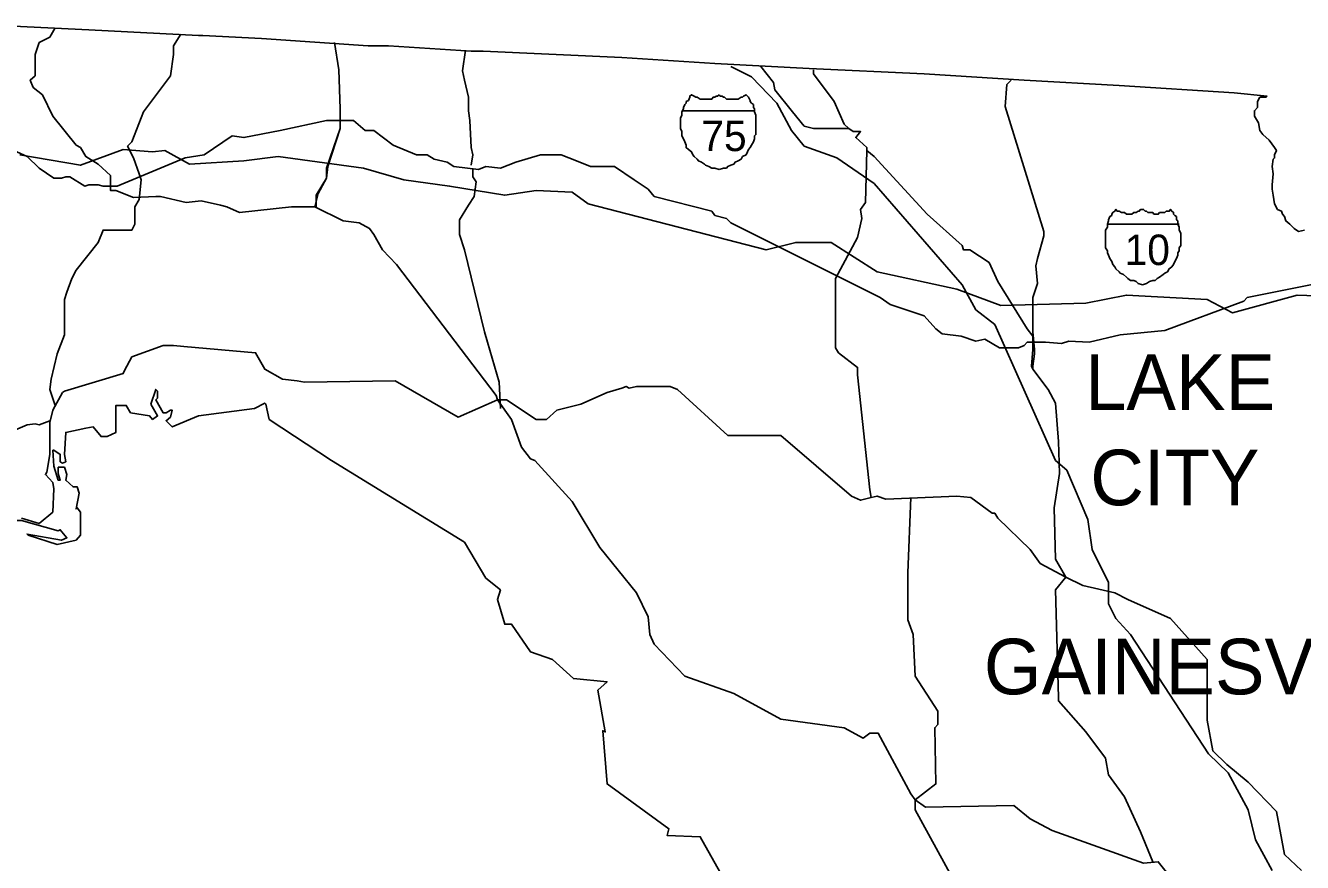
# Model space of a CAD drawing. Extents: x -820.2 to -798.1, y -2199.1 to -2182.2.
# Drawn here: x -807.105 to -806.07, y -2183.909 to -2183.231 of the extents above; entities that cross this region are included whole.
import ezdxf

# ---------------------------------------------------------------- set-up
doc = ezdxf.new("R2010")
doc.units = 0
for name, color, linetype in [('FLMap1', 7, 'Continuous'), ('FLMap2', 7, 'Continuous'), ('FLMap3', 7, 'Continuous'), ('TextMisc', 7, 'Continuous')]:
    doc.layers.add(name, color=color, linetype=linetype)

msp = doc.modelspace()

# ---------------------------------------------------------------- linework, layer by layer
at = {"layer": 'FLMap1'}
for p, q in [((-806.5731, -2183.2999), (-806.5141, -2183.2999)), ((-806.2283, -2183.3917), (-806.1703, -2183.3917))]:
    msp.add_line(p, q, dxfattribs=at)
for points in [[(-806.5429, -2183.287), (-806.5443, -2183.288), (-806.5453, -2183.288), (-806.5463, -2183.289), (-806.5478, -2183.289), (-806.5488, -2183.2905), (-806.5513, -2183.2905), (-806.5523, -2183.2905), (-806.5538, -2183.2905), (-806.5548, -2183.2905), (-806.5558, -2183.2905), (-806.5572, -2183.2905), (-806.5582, -2183.2905), (-806.5607, -2183.289), (-806.5617, -2183.289), (-806.5632, -2183.288), (-806.5652, -2183.287), (-806.5667, -2183.288), (-806.5667, -2183.289), (-806.5677, -2183.2915), (-806.5697, -2183.2925), (-806.5697, -2183.2939), (-806.5706, -2183.2949), (-806.5716, -2183.2974), (-806.5716, -2183.2984), (-806.5731, -2183.3009), (-806.5731, -2183.3034), (-806.5741, -2183.3059), (-806.5741, -2183.3098), (-806.5741, -2183.3123), (-806.5741, -2183.3143), (-806.5731, -2183.3168), (-806.5731, -2183.3192), (-806.5731, -2183.3202), (-806.5716, -2183.3227), (-806.5706, -2183.3252), (-806.5697, -2183.3277), (-806.5697, -2183.3297), (-806.5677, -2183.3312), (-806.5652, -2183.3331), (-806.5642, -2183.3356), (-806.5632, -2183.3371), (-806.5607, -2183.3391), (-806.5597, -2183.3406), (-806.5572, -2183.3416), (-806.5548, -2183.3431), (-806.5538, -2183.3441), (-806.5513, -2183.345), (-806.5488, -2183.3465), (-806.5463, -2183.3465), (-806.5429, -2183.3475)], [(-806.5429, -2183.287), (-806.5419, -2183.288), (-806.5404, -2183.288), (-806.5394, -2183.289), (-806.5384, -2183.289), (-806.5369, -2183.2905), (-806.5359, -2183.2905), (-806.5334, -2183.2905), (-806.5324, -2183.2905), (-806.531, -2183.2905), (-806.53, -2183.2905), (-806.529, -2183.2905), (-806.5275, -2183.2905), (-806.525, -2183.289), (-806.524, -2183.289), (-806.523, -2183.288), (-806.521, -2183.287), (-806.52, -2183.288), (-806.519, -2183.289), (-806.5176, -2183.2915), (-806.5176, -2183.2925), (-806.5166, -2183.2939), (-806.5151, -2183.2949), (-806.5151, -2183.2974), (-806.5141, -2183.2984), (-806.5141, -2183.3009), (-806.5131, -2183.3034), (-806.5131, -2183.3059), (-806.5131, -2183.3098), (-806.5131, -2183.3123), (-806.5131, -2183.3143), (-806.5131, -2183.3168), (-806.5131, -2183.3192), (-806.5141, -2183.3202), (-806.5141, -2183.3227), (-806.5151, -2183.3252), (-806.5166, -2183.3277), (-806.5176, -2183.3297), (-806.519, -2183.3312), (-806.52, -2183.3331), (-806.521, -2183.3356), (-806.524, -2183.3371), (-806.525, -2183.3391), (-806.5275, -2183.3406), (-806.53, -2183.3416), (-806.531, -2183.3431), (-806.5334, -2183.3441), (-806.5359, -2183.345), (-806.5369, -2183.3465), (-806.5394, -2183.3465), (-806.5429, -2183.3475)], [(-806.2, -2183.3798), (-806.2015, -2183.3798), (-806.2025, -2183.3813), (-806.2035, -2183.3813), (-806.205, -2183.3823), (-806.206, -2183.3823), (-806.207, -2183.3823), (-806.2085, -2183.3837), (-806.2095, -2183.3837), (-806.2119, -2183.3837), (-806.2129, -2183.3837), (-806.2144, -2183.3823), (-806.2154, -2183.3823), (-806.2169, -2183.3823), (-806.2189, -2183.3813), (-806.2204, -2183.3813), (-806.2214, -2183.3798), (-806.2224, -2183.3813), (-806.2239, -2183.3823), (-806.2248, -2183.3837), (-806.2248, -2183.3847), (-806.2263, -2183.3857), (-806.2273, -2183.3882), (-806.2273, -2183.3892), (-806.2283, -2183.3917), (-806.2283, -2183.3942), (-806.2298, -2183.3966), (-806.2298, -2183.3991), (-806.2298, -2183.4011), (-806.2298, -2183.4036), (-806.2298, -2183.4066), (-806.2298, -2183.409), (-806.2298, -2183.411), (-806.2283, -2183.4135), (-806.2283, -2183.415), (-806.2273, -2183.417), (-806.2263, -2183.4195), (-806.2248, -2183.4219), (-806.2239, -2183.4244), (-806.2224, -2183.4264), (-806.2214, -2183.4279), (-806.2189, -2183.4304), (-806.2179, -2183.4314), (-806.2154, -2183.4324), (-806.2129, -2183.4348), (-806.2119, -2183.4358), (-806.2095, -2183.4373), (-806.207, -2183.4373), (-806.205, -2183.4383), (-806.2035, -2183.4398), (-806.2, -2183.4408)], [(-806.2, -2183.3798), (-806.199, -2183.3798), (-806.1976, -2183.3813), (-806.1966, -2183.3813), (-806.1956, -2183.3823), (-806.1931, -2183.3823), (-806.1916, -2183.3823), (-806.1906, -2183.3837), (-806.1896, -2183.3837), (-806.1881, -2183.3837), (-806.1871, -2183.3837), (-806.1861, -2183.3823), (-806.1832, -2183.3823), (-806.1817, -2183.3823), (-806.1807, -2183.3813), (-806.1782, -2183.3813), (-806.1772, -2183.3798), (-806.1762, -2183.3813), (-806.1747, -2183.3823), (-806.1747, -2183.3837), (-806.1737, -2183.3847), (-806.1723, -2183.3857), (-806.1723, -2183.3882), (-806.1713, -2183.3892), (-806.1713, -2183.3917), (-806.1703, -2183.3942), (-806.1703, -2183.3966), (-806.1688, -2183.3991), (-806.1688, -2183.4011), (-806.1688, -2183.4036), (-806.1688, -2183.4066), (-806.1688, -2183.409), (-806.1703, -2183.411), (-806.1703, -2183.4135), (-806.1713, -2183.415), (-806.1713, -2183.417), (-806.1723, -2183.4195), (-806.1737, -2183.4219), (-806.1747, -2183.4244), (-806.1762, -2183.4264), (-806.1782, -2183.4279), (-806.1797, -2183.4304), (-806.1817, -2183.4314), (-806.1832, -2183.4324), (-806.1861, -2183.4348), (-806.1881, -2183.4358), (-806.1896, -2183.4373), (-806.1916, -2183.4373), (-806.1941, -2183.4383), (-806.1966, -2183.4398), (-806.2, -2183.4408)]]:
    msp.add_lwpolyline(points, dxfattribs=at)
at = {"layer": 'FLMap2'}
for points in [[(-807.0807, -2183.2329), (-807.0851, -2183.2404), (-807.0936, -2183.2448), (-807.097, -2183.2543), (-807.097, -2183.2632), (-807.097, -2183.2677), (-807.097, -2183.2716), (-807.101, -2183.2751), (-807.0985, -2183.281), (-807.0911, -2183.287), (-807.0826, -2183.3044)], [(-807.0092, -2183.3009), (-806.9874, -2183.2716), (-806.9849, -2183.2543), (-806.9849, -2183.2473), (-806.979, -2183.2379)], [(-806.8544, -2183.2448), (-806.851, -2183.2667), (-806.85, -2183.2984), (-806.85, -2183.3143), (-806.8609, -2183.3465), (-806.8609, -2183.3545), (-806.8678, -2183.3669), (-806.8703, -2183.3778)], [(-806.7483, -2183.2508), (-806.7507, -2183.2677), (-806.7492, -2183.2751), (-806.7458, -2183.289), (-806.7458, -2183.2999), (-806.7448, -2183.3078), (-806.7438, -2183.3297), (-806.7423, -2183.3356), (-806.7438, -2183.3441)], [(-806.5091, -2183.2642), (-806.4987, -2183.2771), (-806.4977, -2183.283), (-806.4833, -2183.3009), (-806.4739, -2183.3123), (-806.4665, -2183.3143), (-806.4377, -2183.3143), (-806.4342, -2183.3168), (-806.4283, -2183.3168), (-806.4322, -2183.3217), (-806.4233, -2183.3297), (-806.4233, -2183.3321), (-806.4173, -2183.3371), (-806.3742, -2183.3837), (-806.3459, -2183.409), (-806.3449, -2183.4125), (-806.3399, -2183.4125), (-806.3241, -2183.4229), (-806.3171, -2183.4383), (-806.2933, -2183.4765), (-806.2888, -2183.4825), (-806.2888, -2183.4934), (-806.2898, -2183.5068), (-806.2888, -2183.5093), (-806.2764, -2183.5256), (-806.2705, -2183.5366), (-806.268, -2183.5678), (-806.267, -2183.5936), (-806.2715, -2183.6214), (-806.2705, -2183.6631), (-806.2621, -2183.6775)], [(-806.4665, -2183.2667), (-806.4665, -2183.2701), (-806.4496, -2183.2925), (-806.4417, -2183.3108), (-806.4377, -2183.3143)], [(-806.3062, -2183.2751), (-806.3097, -2183.2786), (-806.3112, -2183.2964), (-806.2799, -2183.3976), (-806.2799, -2183.4011), (-806.2849, -2183.4195), (-806.2864, -2183.4254), (-806.2849, -2183.4398), (-806.2888, -2183.4512), (-806.2888, -2183.479), (-806.2874, -2183.4934)], [(-807.0807, -2183.5385), (-807.0851, -2183.5256), (-807.0841, -2183.5172), (-807.0792, -2183.4969), (-807.0732, -2183.4815), (-807.0732, -2183.4527), (-807.0712, -2183.4468), (-807.0673, -2183.4358), (-807.0638, -2183.4289), (-807.0459, -2183.4066), (-807.042, -2183.3966), (-807.0186, -2183.3966), (-807.0162, -2183.3917), (-807.0162, -2183.3778), (-807.0127, -2183.3718), (-807.0112, -2183.356), (-807.0127, -2183.351), (-807.0172, -2183.3381), (-807.0221, -2183.3287), (-807.0186, -2183.3252), (-807.0092, -2183.3009)], [(-807.1119, -2183.3331), (-807.1035, -2183.3371), (-807.0936, -2183.3465), (-807.0817, -2183.3545), (-807.0757, -2183.3545), (-807.0722, -2183.3535), (-807.0688, -2183.3535), (-807.0568, -2183.3609), (-807.0534, -2183.3599), (-807.0459, -2183.3599), (-807.042, -2183.3609), (-807.0306, -2183.3609), (-806.9755, -2183.3381), (-806.9601, -2183.3356), (-806.9373, -2183.3202), (-806.9279, -2183.3217), (-806.8986, -2183.3158), (-806.8609, -2183.3078), (-806.839, -2183.3078), (-806.8296, -2183.3158)], [(-806.5954, -2183.732), (-806.5989, -2183.7241), (-806.6004, -2183.7097), (-806.6098, -2183.6903), (-806.6396, -2183.6536), (-806.6619, -2183.6164), (-806.6922, -2183.5832), (-806.6957, -2183.5817), (-806.7031, -2183.5723), (-806.711, -2183.5499), (-806.7225, -2183.5341), (-806.7234, -2183.5306), (-806.8043, -2183.4244), (-806.8157, -2183.4125), (-806.8227, -2183.4001), (-806.8261, -2183.3952), (-806.8346, -2183.3907), (-806.8475, -2183.3892), (-806.8703, -2183.3778), (-806.8892, -2183.3778), (-806.9313, -2183.3823), (-806.9417, -2183.3778), (-806.9467, -2183.3763), (-806.9626, -2183.3728), (-806.9745, -2183.3743), (-806.9953, -2183.3694), (-806.9993, -2183.3694), (-807.0172, -2183.3703), (-807.0315, -2183.3644), (-807.036, -2183.3644), (-807.036, -2183.3525), (-807.0459, -2183.3431), (-807.0559, -2183.3371), (-807.0603, -2183.3297), (-807.0638, -2183.3277), (-807.0826, -2183.3044)], [(-806.8693, -2183.3778), (-806.8693, -2183.3684), (-806.8609, -2183.3545), (-806.8599, -2183.345), (-806.85, -2183.3143)], [(-806.8296, -2183.3158), (-806.8252, -2183.3158), (-806.8227, -2183.3158), (-806.8068, -2183.3277), (-806.7879, -2183.3356), (-806.7795, -2183.3356), (-806.7736, -2183.3391), (-806.7631, -2183.3416), (-806.7577, -2183.345), (-806.7378, -2183.3475), (-806.7319, -2183.345), (-806.72, -2183.3465), (-806.7076, -2183.3416), (-806.6877, -2183.3356), (-806.6709, -2183.3356), (-806.6585, -2183.3406), (-806.647, -2183.345), (-806.6277, -2183.345), (-806.6118, -2183.356), (-806.6004, -2183.3634), (-806.5954, -2183.3694), (-806.5488, -2183.3813), (-806.5463, -2183.3847), (-806.5369, -2183.3872), (-806.5334, -2183.3907), (-806.4124, -2183.4512), (-806.4044, -2183.4567), (-806.3767, -2183.4661), (-806.3672, -2183.4765), (-806.3623, -2183.4805), (-806.3469, -2183.4825), (-806.335, -2183.4864), (-806.3275, -2183.485), (-806.3156, -2183.4919), (-806.3003, -2183.4919), (-806.2958, -2183.4899), (-806.2933, -2183.4874), (-806.2784, -2183.4874), (-806.2655, -2183.4884), (-806.2596, -2183.4864), (-806.2432, -2183.4874)], [(-806.4233, -2183.3321), (-806.4243, -2183.3743), (-806.4283, -2183.3798), (-806.4273, -2183.3872), (-806.4307, -2183.4026), (-806.4486, -2183.4358), (-806.4486, -2183.4919), (-806.4461, -2183.4959), (-806.4307, -2183.5078), (-806.4307, -2183.5137), (-806.4208, -2183.607), (-806.4198, -2183.613)], [(-806.72, -2183.541), (-806.721, -2183.5197), (-806.7304, -2183.4874), (-806.7329, -2183.479), (-806.7492, -2183.4125), (-806.7532, -2183.4001), (-806.7532, -2183.3882), (-806.7458, -2183.3763), (-806.7413, -2183.3694), (-806.7398, -2183.3575), (-806.7423, -2183.3535), (-806.7423, -2183.3475)], [(-806.2432, -2183.4874), (-806.2179, -2183.4815), (-806.1817, -2183.478), (-806.1177, -2183.4542), (-806.1152, -2183.4512), (-806.0219, -2183.4324), (-806.0041, -2183.4264), (-805.9812, -2183.4279), (-805.8905, -2183.4205), (-805.8503, -2183.415), (-805.8403, -2183.416), (-805.8294, -2183.4205), (-805.8026, -2183.4205), (-805.7962, -2183.4229), (-805.7962, -2183.4398)], [(-807.0747, -2183.5281), (-807.0732, -2183.5271), (-807.0256, -2183.5127), (-807.0246, -2183.5103), (-807.0186, -2183.4993), (-806.9933, -2183.4899), (-806.9849, -2183.4899), (-806.9765, -2183.4909), (-806.9184, -2183.4959), (-806.9184, -2183.4959), (-806.911, -2183.5093), (-806.8966, -2183.5172), (-806.8966, -2183.5172), (-806.8847, -2183.5187), (-806.8787, -2183.5197), (-806.8053, -2183.5187), (-806.7542, -2183.548), (-806.7225, -2183.5341), (-806.715, -2183.5341), (-806.6912, -2183.5499), (-806.6828, -2183.5499), (-806.6743, -2183.5425), (-806.655, -2183.5375), (-806.6337, -2183.5281), (-806.6217, -2183.5246)], [(-806.2874, -2183.4934), (-806.2874, -2183.4969), (-806.2888, -2183.5068), (-806.2888, -2183.5093)], [(-807.1079, -2183.6298), (-807.0936, -2183.6343), (-807.0826, -2183.6249), (-807.0817, -2183.606), (-807.0826, -2183.601), (-807.0886, -2183.5946), (-807.0876, -2183.5926), (-807.0851, -2183.5782), (-807.0851, -2183.5534), (-807.0851, -2183.5524), (-807.0826, -2183.5425), (-807.0747, -2183.5281)], [(-807.0033, -2183.5375), (-806.9993, -2183.5256), (-806.9978, -2183.5271), (-806.9978, -2183.5326), (-806.9993, -2183.5341), (-806.9933, -2183.5445), (-806.9909, -2183.5445), (-806.9874, -2183.5425), (-806.9859, -2183.5425), (-806.9874, -2183.548), (-806.9909, -2183.5509), (-806.9859, -2183.5559), (-806.9646, -2183.547), (-806.9194, -2183.541), (-806.911, -2183.5366), (-806.91, -2183.5375), (-806.9075, -2183.5499), (-806.8569, -2183.5832)], [(-806.6217, -2183.5246), (-806.6183, -2183.5232), (-806.6158, -2183.5246), (-806.6098, -2183.5232), (-806.5826, -2183.5232), (-806.5766, -2183.5256), (-806.5359, -2183.5628), (-806.4928, -2183.5628), (-806.4357, -2183.612), (-806.4283, -2183.6154), (-806.4198, -2183.613)], [(-807.0792, -2183.6512), (-807.0638, -2183.6477), (-807.0603, -2183.6437), (-807.0603, -2183.6249), (-807.0628, -2183.6214), (-807.0638, -2183.6224), (-807.0613, -2183.6095), (-807.0628, -2183.6045), (-807.0663, -2183.6045), (-807.0722, -2183.5991), (-807.0712, -2183.5946), (-807.0732, -2183.5886), (-807.0782, -2183.5886), (-807.0782, -2183.5936), (-807.0767, -2183.5991), (-807.0782, -2183.5991), (-807.0817, -2183.5877), (-807.0826, -2183.5748), (-807.0817, -2183.5748), (-807.0767, -2183.5782), (-807.0767, -2183.5842), (-807.0747, -2183.5852), (-807.0722, -2183.5842), (-807.0732, -2183.5782), (-807.0722, -2183.5604), (-807.0559, -2183.5569), (-807.0499, -2183.5559), (-807.0435, -2183.5638), (-807.0385, -2183.5638), (-807.0315, -2183.5604), (-807.0315, -2183.5385), (-807.0231, -2183.5385), (-807.0196, -2183.5445), (-807.0043, -2183.547), (-807.0018, -2183.5499), (-806.9978, -2183.547), (-807.0033, -2183.5375)], [(-807.1447, -2183.6368), (-807.1427, -2183.6318), (-807.1352, -2183.6259), (-807.1367, -2183.6189), (-807.1342, -2183.6095), (-807.1352, -2183.6001), (-807.1367, -2183.5936), (-807.1308, -2183.5653), (-807.1293, -2183.5628), (-807.1233, -2183.5619), (-807.1164, -2183.5584), (-807.1129, -2183.5584), (-807.1035, -2183.5544), (-807.097, -2183.5534), (-807.0936, -2183.5544), (-807.0851, -2183.5509)], [(-806.8569, -2183.5832), (-806.7492, -2183.6492), (-806.7319, -2183.6784), (-806.72, -2183.6879), (-806.7225, -2183.6958), (-806.7165, -2183.7157), (-806.711, -2183.7157), (-806.6957, -2183.738), (-806.6778, -2183.7444), (-806.6609, -2183.7598), (-806.6337, -2183.7623), (-806.6411, -2183.7692)], [(-806.4198, -2183.613), (-806.4149, -2183.612), (-806.4079, -2183.6144), (-806.3504, -2183.612), (-806.339, -2183.613), (-806.3216, -2183.6259), (-806.3196, -2183.6259), (-806.3171, -2183.6298), (-806.2908, -2183.6551), (-806.2829, -2183.6665), (-806.2621, -2183.6775), (-806.2482, -2183.6844), (-806.2224, -2183.6903), (-806.2119, -2183.6958)], [(-806.3841, -2183.858), (-806.3672, -2183.8451), (-806.3682, -2183.7995), (-806.3657, -2183.797), (-806.3657, -2183.7861), (-806.3841, -2183.7578), (-806.3856, -2183.7241), (-806.3901, -2183.7122), (-806.3901, -2183.674), (-806.3876, -2183.613)], [(-807.1387, -2183.6378), (-807.1318, -2183.6402), (-807.1318, -2183.6402), (-807.1139, -2183.6318), (-807.1079, -2183.6318), (-807.0782, -2183.6402), (-807.0767, -2183.6392), (-807.0712, -2183.6457), (-807.0757, -2183.6477), (-807.1035, -2183.6427), (-807.1025, -2183.6437), (-807.0792, -2183.6512)], [(-806.2621, -2183.6775), (-806.2705, -2183.6879), (-806.268, -2183.7752), (-806.268, -2183.7777), (-806.2457, -2183.803), (-806.2298, -2183.8243), (-806.2273, -2183.8377), (-806.2144, -2183.8556), (-806.2015, -2183.8838), (-806.1916, -2183.9081)], [(-806.2119, -2183.6958), (-806.1772, -2183.7112), (-806.1474, -2183.7444), (-806.1474, -2183.7935), (-806.143, -2183.8183), (-806.1316, -2183.8293), (-806.1142, -2183.8437), (-806.0914, -2183.8675), (-806.0849, -2183.9022), (-806.071, -2183.9151)], [(-806.5954, -2183.732), (-806.5706, -2183.7578), (-806.531, -2183.7717), (-806.4928, -2183.7926), (-806.4417, -2183.7995), (-806.4417, -2183.7995), (-806.4263, -2183.8079), (-806.4208, -2183.804), (-806.4139, -2183.804), (-806.3876, -2183.8531), (-806.3841, -2183.858), (-806.3841, -2183.866), (-806.3003, -2184.0188)], [(-806.6411, -2183.7692), (-806.6351, -2183.803), (-806.6371, -2183.802), (-806.6337, -2183.8451), (-806.5835, -2183.8814), (-806.585, -2183.8868), (-806.5582, -2183.8878), (-806.524, -2183.9488), (-806.529, -2183.9573), (-806.4868, -2183.9771), (-806.4764, -2183.992), (-806.4843, -2183.9999), (-806.4749, -2184.0262), (-806.4511, -2184.0262), (-806.3672, -2184.0337), (-806.3588, -2184.0287), (-806.3623, -2184.0619)], [(-806.3841, -2183.858), (-806.3757, -2183.864), (-806.3042, -2183.8625), (-806.2908, -2183.8734), (-806.273, -2183.8828), (-806.199, -2183.9091), (-806.1871, -2183.9081), (-806.1762, -2183.922), (-806.1405, -2183.9712), (-806.1365, -2183.9771), (-806.1142, -2183.992), (-806.1127, -2183.993), (-806.0949, -2183.9955), (-806.0745, -2184.0059), (-806.0686, -2184.0108), (-806.0557, -2184.0118)]]:
    msp.add_lwpolyline(points, dxfattribs=at)
at = {"layer": 'FLMap3'}
for points in [[(-807.1258, -2183.2309), (-807.0534, -2183.2344), (-806.9646, -2183.2389), (-806.9611, -2183.2389)], [(-806.9611, -2183.2389), (-806.9135, -2183.2414), (-806.8271, -2183.2473), (-806.8108, -2183.2473)], [(-806.8108, -2183.2473), (-806.7438, -2183.2518), (-806.7339, -2183.2518), (-806.7339, -2183.2518), (-806.6217, -2183.2567), (-806.5463, -2183.2617), (-806.4699, -2183.2657), (-806.3767, -2183.2701), (-806.2958, -2183.2751), (-806.2189, -2183.2796), (-806.1256, -2183.2855), (-806.0988, -2183.288)], [(-806.5334, -2183.2642), (-806.5166, -2183.2726), (-806.4962, -2183.2939), (-806.4843, -2183.3158), (-806.4739, -2183.3287), (-806.4476, -2183.3381), (-806.4173, -2183.3589), (-806.3459, -2183.4408), (-806.335, -2183.4611), (-806.3196, -2183.473), (-806.2705, -2183.5832)], [(-806.0988, -2183.288), (-806.0998, -2183.289), (-806.1048, -2183.289), (-806.1068, -2183.2925), (-806.1068, -2183.2974), (-806.1092, -2183.2999), (-806.1092, -2183.3044), (-806.1058, -2183.3098), (-806.1048, -2183.3158), (-806.1023, -2183.3192), (-806.0973, -2183.3237), (-806.0929, -2183.3297), (-806.0914, -2183.3321), (-806.0929, -2183.3356), (-806.0929, -2183.3381), (-806.0939, -2183.3391), (-806.0949, -2183.345), (-806.0939, -2183.351), (-806.0949, -2183.3599), (-806.0949, -2183.3634), (-806.0939, -2183.3684), (-806.0929, -2183.3753), (-806.0904, -2183.3798), (-806.0874, -2183.3813), (-806.0864, -2183.3837), (-806.0849, -2183.3857), (-806.0839, -2183.3892), (-806.0805, -2183.3917), (-806.077, -2183.3952), (-806.0735, -2183.3976), (-806.0686, -2183.3966)], [(-807.1094, -2183.3356), (-807.0603, -2183.3441), (-807.0256, -2183.3312), (-807.0018, -2183.3331), (-806.9919, -2183.3321), (-806.972, -2183.3431), (-806.9279, -2183.3406), (-806.9001, -2183.3371), (-806.8311, -2183.3465), (-806.7984, -2183.356), (-806.7612, -2183.3609), (-806.7165, -2183.3684), (-806.6912, -2183.3644), (-806.6619, -2183.3659), (-806.649, -2183.3753), (-806.5047, -2183.4125), (-806.4808, -2183.4066), (-806.4521, -2183.4066), (-806.4149, -2183.4304), (-806.3504, -2183.4443), (-806.3146, -2183.4577), (-806.2457, -2183.4557), (-806.2129, -2183.4492), (-806.1474, -2183.4527), (-806.1271, -2183.4636), (-806.0745, -2183.4492), (-806.0507, -2183.4502)], [(-806.2705, -2183.5832), (-806.2611, -2183.5911), (-806.2442, -2183.6308), (-806.2407, -2183.6551), (-806.2273, -2183.6819), (-806.2273, -2183.6993), (-806.2214, -2183.7112), (-806.2095, -2183.7241), (-806.1465, -2183.8208), (-806.1306, -2183.8362), (-806.1142, -2183.866), (-806.1083, -2183.8903), (-806.0949, -2183.9151)]]:
    msp.add_lwpolyline(points, dxfattribs=at)

# ---------------------------------------------------------------- texts
at = {"layer": 'TextMisc'}
for s, height, p in [('75', 0.0247, (-806.5573, -2183.3326)), ('10', 0.0247, (-806.2144, -2183.4249)), ('LAKE ', 0.045, (-806.2464, -2183.5422)), ('CITY', 0.045, (-806.2422, -2183.6194)), ('GAINESVILLE', 0.045, (-806.3284, -2183.7725))]:
    msp.add_text(s, height=height, dxfattribs=at).set_placement(p)

doc.saveas('drawing.dxf')
